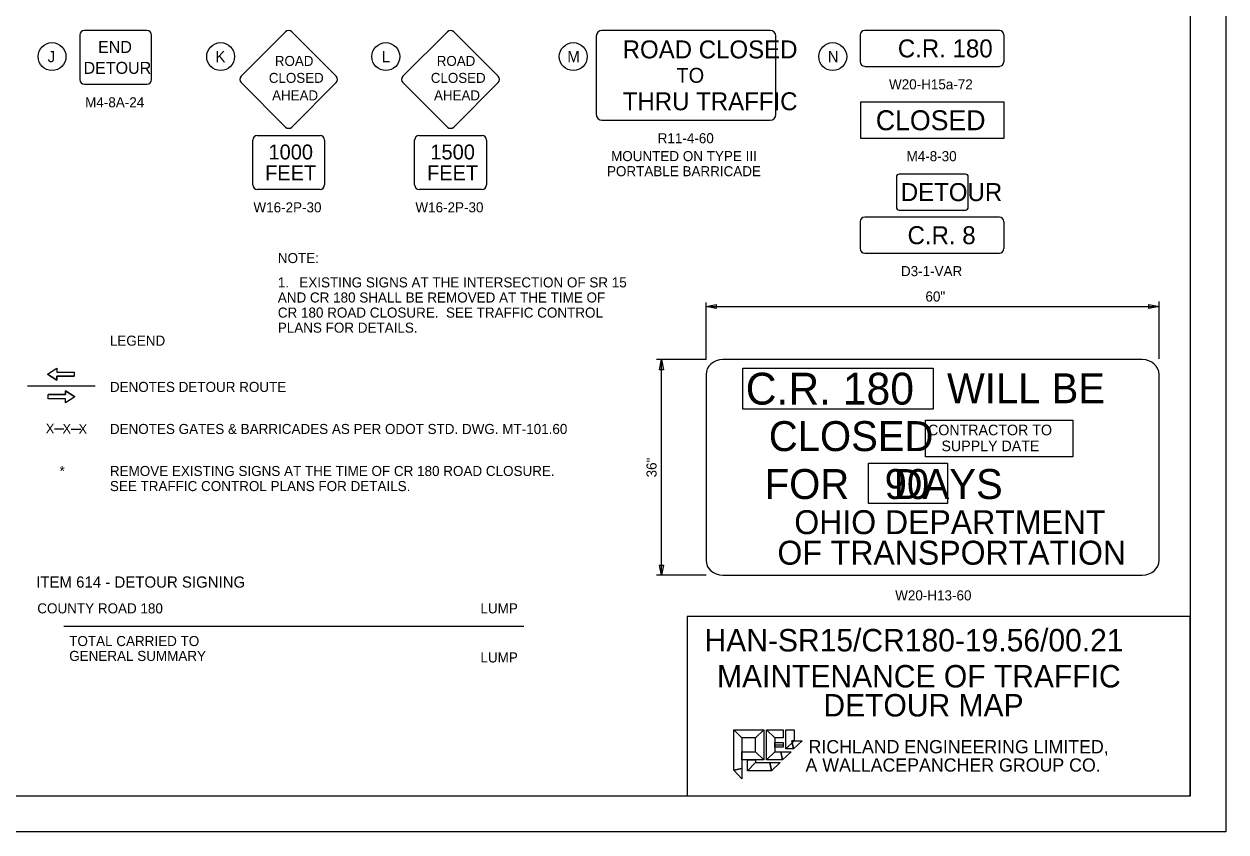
# Model space of a CAD drawing. Extents: x 1651.5 to 1685.5, y 1084.6 to 1106.6.
# Drawn here: x 1668.74 to 1685.46, y 1084.6 to 1095.85 of the extents above; entities that cross this region are included whole.
import ezdxf

# ---------------------------------------------------------------- set-up
doc = ezdxf.new("R2010")
doc.units = 0
for name, color, linetype in [('SC_Scratch1', 7, 'Continuous'), ('SH_Border', 7, 'Continuous'), ('SH_Data', 7, 'Continuous'), ('SH_Text', 7, 'Continuous'), ('SN_P_Signs', 7, 'Continuous'), ('SN_P_Text', 7, 'Continuous')]:
    doc.layers.add(name, color=color, linetype=linetype)

msp = doc.modelspace()

# ---------------------------------------------------------------- linework, layer by layer
at = {"layer": 'SC_Scratch1'}
msp.add_lwpolyline([(1651.463, 1106.601), (1685.463, 1106.601), (1685.463, 1084.601), (1651.463, 1084.601)], close=True, dxfattribs=at)
at = {"layer": 'SH_Border'}
for p, q in [((1684.963, 1087.601), (1677.963, 1087.601)), ((1677.963, 1087.601), (1677.963, 1085.101)), ((1684.963, 1085.101), (1684.963, 1087.601))]:
    msp.add_line(p, q, dxfattribs=at)
msp.add_lwpolyline([(1651.963, 1106.101), (1684.963, 1106.101), (1684.963, 1085.101), (1651.963, 1085.101)], close=True, dxfattribs=at)
at = {"layer": 'SH_Text'}
for p, q in [((1678.227, 1091.175), (1678.227, 1091.972)), ((1684.532, 1091.186), (1684.532, 1091.984)), ((1678.227, 1091.914), (1684.532, 1091.914)), ((1678.227, 1091.175), (1677.539, 1091.175)), ((1677.609, 1088.175), (1677.609, 1091.175)), ((1669.064, 1090.974), (1669.192, 1091.058)), ((1669.064, 1090.974), (1669.191, 1090.889)), ((1669.191, 1090.889), (1669.191, 1090.943)), ((1669.191, 1090.943), (1669.433, 1090.943)), ((1669.192, 1091.058), (1669.192, 1091.002)), ((1669.192, 1091.002), (1669.434, 1091.001)), ((1669.434, 1091.001), (1669.433, 1090.943)), ((1669.727, 1090.807), (1668.784, 1090.807)), ((1669.314, 1090.689), (1669.072, 1090.689)), ((1669.072, 1090.631), (1669.072, 1090.689)), ((1669.314, 1090.63), (1669.072, 1090.631)), ((1669.441, 1090.658), (1669.314, 1090.743)), ((1669.314, 1090.743), (1669.314, 1090.689)), ((1669.441, 1090.658), (1669.314, 1090.573)), ((1669.314, 1090.573), (1669.314, 1090.63)), ((1678.227, 1088.175), (1677.539, 1088.175)), ((1675.694, 1087.459), (1669.288, 1087.459)), ((1679.185, 1085.814), (1679.299, 1085.814))]:
    msp.add_line(p, q, dxfattribs=at)
for points in [[(1678.367, 1091.886), (1678.227, 1091.914), (1678.367, 1091.942)], [(1684.392, 1091.942), (1684.532, 1091.914), (1684.392, 1091.886)], [(1677.581, 1091.035), (1677.609, 1091.175), (1677.637, 1091.035)], [(1669.433, 1090.943), (1669.191, 1090.943), (1669.191, 1090.889), (1669.064, 1090.974), (1669.192, 1091.058), (1669.192, 1091.001), (1669.434, 1091.001)], [(1678.741, 1091.055), (1681.389, 1091.055), (1681.389, 1090.486), (1678.741, 1090.486)], [(1669.072, 1090.689), (1669.314, 1090.689), (1669.314, 1090.743), (1669.441, 1090.658), (1669.314, 1090.573), (1669.314, 1090.63), (1669.072, 1090.631)], [(1681.283, 1090.334), (1683.332, 1090.334), (1683.332, 1089.822), (1681.283, 1089.822)], [(1680.488, 1089.735), (1681.59, 1089.735), (1681.59, 1089.171), (1680.488, 1089.171)], [(1677.637, 1088.315), (1677.609, 1088.175), (1677.581, 1088.315)], [(1678.613, 1085.459), (1678.613, 1086.023), (1678.728, 1085.909), (1678.728, 1085.482)], [(1678.613, 1086.023), (1679.033, 1086.023), (1678.918, 1085.909), (1678.728, 1085.909)], [(1679.033, 1086.023), (1679.033, 1085.604), (1678.918, 1085.718), (1678.918, 1085.909)], [(1679.071, 1085.604), (1679.071, 1086.023), (1679.185, 1085.909), (1679.185, 1085.718)], [(1679.071, 1086.023), (1679.299, 1086.023), (1679.299, 1085.909), (1679.185, 1085.909)], [(1679.337, 1085.756), (1679.337, 1086.023), (1679.452, 1086.023), (1679.452, 1085.871)], [(1679.299, 1085.848), (1679.299, 1085.779), (1679.186, 1085.779), (1679.186, 1085.848)], [(1679.445, 1085.756), (1679.337, 1085.756), (1679.452, 1085.871), (1679.421, 1085.871)], [(1679.566, 1085.871), (1679.445, 1085.756), (1679.421, 1085.871)], [(1679.033, 1085.604), (1678.728, 1085.604), (1678.728, 1085.718), (1678.918, 1085.718)], [(1678.804, 1085.452), (1678.804, 1085.604), (1678.918, 1085.604), (1678.918, 1085.566)], [(1679.292, 1085.604), (1679.071, 1085.604), (1679.185, 1085.718), (1679.268, 1085.718)], [(1679.413, 1085.718), (1679.292, 1085.604), (1679.268, 1085.718)], [(1678.728, 1085.338), (1678.613, 1085.459), (1678.728, 1085.482)], [(1679.139, 1085.452), (1678.804, 1085.452), (1678.918, 1085.566), (1679.116, 1085.566)], [(1679.261, 1085.566), (1679.139, 1085.452), (1679.116, 1085.566)]]:
    msp.add_lwpolyline(points, close=True, dxfattribs=at)
for centre in [(1669.126, 1095.393), (1671.472, 1095.393), (1673.771, 1095.393), (1676.379, 1095.393), (1679.991, 1095.393)]:
    msp.add_circle(centre, 0.194, dxfattribs=at)
at = {"layer": 'SN_P_Signs'}
for p, q in [((1684.299, 1091.175), (1678.46, 1091.175)), ((1678.227, 1090.967), (1678.227, 1088.383)), ((1684.532, 1088.383), (1684.532, 1090.967)), ((1669.161, 1090.212), (1669.291, 1090.21)), ((1669.391, 1090.209), (1669.528, 1090.207)), ((1678.46, 1088.175), (1684.299, 1088.175))]:
    msp.add_line(p, q, dxfattribs=at)
for points in [[(1669.512, 1095.692), (1669.512, 1095.072)], [(1670.447, 1095.757), (1669.577, 1095.757)], [(1670.512, 1095.072), (1670.512, 1095.692)], [(1671.756, 1095.12), (1672.375, 1095.739)], [(1672.463, 1095.739), (1673.082, 1095.12)], [(1674.009, 1095.12), (1674.628, 1095.739)], [(1674.717, 1095.739), (1675.335, 1095.12)], [(1676.7, 1095.679), (1676.7, 1094.585)], [(1679.122, 1095.757), (1676.778, 1095.757)], [(1679.2, 1094.585), (1679.2, 1095.679)], [(1680.373, 1095.695), (1680.373, 1095.32)], [(1682.311, 1095.757), (1680.436, 1095.757)], [(1682.373, 1095.695), (1682.373, 1095.32)], [(1680.436, 1095.257), (1682.311, 1095.257)], [(1669.577, 1095.007), (1670.447, 1095.007)], [(1672.375, 1094.413), (1671.756, 1095.032)], [(1673.082, 1095.032), (1672.463, 1094.413)], [(1674.628, 1094.413), (1674.009, 1095.032)], [(1675.335, 1095.032), (1674.717, 1094.413)], [(1676.778, 1094.507), (1679.122, 1094.507)], [(1671.982, 1094.295), (1672.857, 1094.295)], [(1674.235, 1094.295), (1675.11, 1094.295)], [(1671.919, 1093.607), (1671.919, 1094.232)], [(1672.919, 1094.232), (1672.919, 1093.607)], [(1674.172, 1093.607), (1674.172, 1094.232)], [(1675.172, 1094.232), (1675.172, 1093.607)], [(1680.877, 1093.717), (1680.877, 1093.297)], [(1681.837, 1093.757), (1680.917, 1093.757)], [(1681.877, 1093.297), (1681.877, 1093.717)], [(1672.857, 1093.545), (1671.982, 1093.545)], [(1675.11, 1093.545), (1674.235, 1093.545)], [(1682.311, 1093.157), (1680.436, 1093.157)], [(1680.917, 1093.257), (1681.837, 1093.257)], [(1680.373, 1093.095), (1680.373, 1092.72)], [(1682.373, 1093.095), (1682.373, 1092.72)], [(1680.436, 1092.657), (1682.311, 1092.657)]]:
    msp.add_lwpolyline(points, dxfattribs=at)
msp.add_lwpolyline([(1680.377, 1094.257), (1682.377, 1094.257), (1682.377, 1094.757), (1680.377, 1094.757)], close=True, dxfattribs=at)
for centre, radius, start, end in [((1669.577, 1095.692), 0.065, 90, 180), ((1670.447, 1095.692), 0.065, 0, 90), ((1672.419, 1095.695), 0.0625, 45, 135), ((1674.672, 1095.695), 0.0625, 45, 135), ((1676.778, 1095.679), 0.0781, 90, 180), ((1679.122, 1095.679), 0.0781, 0, 90), ((1680.436, 1095.695), 0.0625, 90, 180), ((1682.311, 1095.695), 0.0625, 0, 90), ((1680.436, 1095.32), 0.0625, 180, 270), ((1682.311, 1095.32), 0.0625, 270, 0), ((1671.8, 1095.076), 0.0625, 135, 225), ((1673.038, 1095.076), 0.0625, 315, 45), ((1674.054, 1095.076), 0.0625, 135, 225), ((1675.291, 1095.076), 0.0625, 315, 45), ((1669.577, 1095.072), 0.065, 180, 270), ((1670.447, 1095.072), 0.065, 270, 0), ((1676.778, 1094.585), 0.0781, 180, 270), ((1679.122, 1094.585), 0.0781, 270, 0), ((1671.982, 1094.232), 0.0625, 90, 180), ((1672.419, 1094.457), 0.0625, 225, 315), ((1672.857, 1094.232), 0.0625, 0, 90), ((1674.235, 1094.232), 0.0625, 90, 180), ((1674.672, 1094.457), 0.0625, 225, 315), ((1675.11, 1094.232), 0.0625, 0, 90), ((1680.917, 1093.717), 0.04, 90, 180), ((1681.837, 1093.717), 0.04, 0, 90), ((1671.982, 1093.607), 0.0625, 180, 270), ((1672.857, 1093.607), 0.0625, 270, 0), ((1674.235, 1093.607), 0.0625, 180, 270), ((1675.11, 1093.607), 0.0625, 270, 0), ((1680.917, 1093.297), 0.04, 180, 270), ((1681.837, 1093.297), 0.04, 270, 0), ((1680.436, 1093.095), 0.0625, 90, 180), ((1682.311, 1093.095), 0.0625, 0, 90), ((1680.436, 1092.72), 0.0625, 180, 270), ((1682.311, 1092.72), 0.0625, 270, 0)]:
    msp.add_arc(centre, radius, start, end, dxfattribs=at)
for centre, major_axis, start_param, end_param in [((1678.46, 1090.967), (-0.233, 0), 4.712389, 6.283185), ((1684.299, 1090.967), (0.233, 0), 0, 1.570796), ((1678.46, 1088.383), (-0.233, 0), 0, 1.570796), ((1684.299, 1088.383), (0.233, 0), 4.712389, 6.283185)]:
    msp.add_ellipse(centre, major_axis=major_axis, ratio=0.891693, start_param=start_param, end_param=end_param, dxfattribs=at)

# ---------------------------------------------------------------- texts
at = {"layer": 'SH_Data'}
for s, p in [('HAN-SR15/CR180-19.56/00.21', (1678.207, 1087.113)), ('MAINTENANCE OF TRAFFIC', (1678.38, 1086.612)), ('DETOUR MAP', (1679.861, 1086.208))]:
    msp.add_text(s, height=0.3125, rotation=360, dxfattribs=at).set_placement(p)
at = {"layer": 'SH_Text'}
for s, height, p in [('J', 0.156, (1669.065, 1095.315)), ('K', 0.156, (1671.399, 1095.315)), ('L', 0.156, (1673.715, 1095.315)), ('M', 0.156, (1676.297, 1095.315)), ('N', 0.156, (1679.921, 1095.315)), ('NOTE:', 0.14, (1672.268, 1092.519)), ('1.', 0.14, (1672.268, 1092.18)), ('EXISTING SIGNS AT THE INTERSECTION OF SR 15', 0.14, (1672.568, 1092.18)), ('AND CR 180 SHALL BE REMOVED AT THE TIME OF', 0.14, (1672.268, 1091.97)), ('60"', 0.14, (1681.281, 1091.984)), ('CR 180 ROAD CLOSURE.  SEE TRAFFIC CONTROL', 0.14, (1672.268, 1091.76)), ('PLANS FOR DETAILS.', 0.14, (1672.268, 1091.55)), ('LEGEND', 0.14, (1669.931, 1091.369)), ('C.R. 180', 0.4437, (1678.78, 1090.549)), ('WILL BE', 0.4167, (1681.581, 1090.568)), ('DENOTES DETOUR ROUTE', 0.14, (1669.931, 1090.725)), ('DENOTES GATES & BARRICADES AS PER ODOT STD. DWG. MT-101.60', 0.14, (1669.931, 1090.14)), ('CLOSED', 0.4167, (1679.101, 1089.902)), ('CONTRACTOR TO', 0.14793, (1681.317, 1090.122)), ('SUPPLY DATE', 0.14793, (1681.504, 1089.9)), ('*', 0.14, (1669.231, 1089.555)), ('REMOVE EXISTING SIGNS AT THE TIME OF CR 180 ROAD CLOSURE.', 0.14, (1669.931, 1089.555)), ('FOR    DAYS', 0.41667, (1679.044, 1089.235)), ('90', 0.4167, (1680.713, 1089.235)), ('SEE TRAFFIC CONTROL PLANS FOR DETAILS.', 0.14, (1669.931, 1089.345)), ('ITEM 614 - DETOUR SIGNING', 0.156, (1668.905, 1088.001)), ('W20-H13-60', 0.14, (1680.86, 1087.824)), ('COUNTY ROAD 180', 0.14, (1668.921, 1087.643)), ('LUMP', 0.14, (1675.088, 1087.643)), ('TOTAL CARRIED TO', 0.14, (1669.365, 1087.188)), ('GENERAL SUMMARY', 0.14, (1669.365, 1086.981)), ('LUMP', 0.14, (1675.088, 1086.96))]:
    msp.add_text(s, height=height, dxfattribs=at).set_placement(p)
for s, height, rotation, p in [('36"', 0.14, 90, (1677.539, 1089.536)), ('RICHLAND ENGINEERING LIMITED,', 0.1849, 360, (1679.655, 1085.695)), ('A WALLACEPANCHER GROUP CO.', 0.1849, 360, (1679.612, 1085.44))]:
    msp.add_text(s, height=height, rotation=rotation, dxfattribs=at).set_placement(p)
at = {"layer": 'SN_P_Signs'}
for s, height, p in [('ROAD CLOSED', 0.25, (1677.067, 1095.368)), ('C.R. 180', 0.25, (1680.897, 1095.382)), ('END', 0.1667, (1669.767, 1095.444)), ('DETOUR', 0.1667, (1669.565, 1095.153)), ('ROAD', 0.1389, (1672.227, 1095.263)), ('ROAD', 0.1389, (1674.48, 1095.263)), ('CLOSED', 0.1389, (1672.143, 1095.027)), ('CLOSED', 0.1389, (1674.397, 1095.027)), ('TO', 0.2083, (1677.815, 1095.028)), ('AHEAD', 0.1389, (1672.189, 1094.784)), ('AHEAD', 0.1389, (1674.442, 1094.784)), ('THRU TRAFFIC', 0.25, (1677.068, 1094.646)), ('CLOSED', 0.2778, (1680.59, 1094.368)), ('1000', 0.2083, (1672.138, 1093.961)), ('1500', 0.2083, (1674.391, 1093.961)), ('FEET', 0.2083, (1672.091, 1093.67)), ('FEET', 0.2083, (1674.345, 1093.67)), ('DETOUR', 0.25, (1680.938, 1093.382)), ('C.R. 8', 0.25, (1681.032, 1092.782)), ('OHIO DEPARTMENT', 0.33317, (1679.456, 1088.746)), ('OF TRANSPORTATION', 0.33317, (1679.221, 1088.321))]:
    msp.add_text(s, height=height, dxfattribs=at).set_placement(p)
for p in [(1669.038, 1090.15), (1669.271, 1090.147), (1669.495, 1090.144)]:
    msp.add_text('X', height=0.133, rotation=359.2514, dxfattribs=at).set_placement(p)
at = {"layer": 'SN_P_Text'}
for s, p in [('W20-H15a-72', (1680.774, 1094.937)), ('M4-8A-24', (1669.587, 1094.687)), ('R11-4-60', (1677.555, 1094.187)), ('MOUNTED ON TYPE III', (1676.906, 1093.938)), ('M4-8-30', (1681.018, 1093.937)), ('PORTABLE BARRICADE', (1676.849, 1093.728)), ('W16-2P-30', (1671.929, 1093.225)), ('W16-2P-30', (1674.183, 1093.225)), ('D3-1-VAR', (1680.94, 1092.337))]:
    msp.add_text(s, height=0.14, dxfattribs=at).set_placement(p)

doc.saveas('drawing.dxf')
